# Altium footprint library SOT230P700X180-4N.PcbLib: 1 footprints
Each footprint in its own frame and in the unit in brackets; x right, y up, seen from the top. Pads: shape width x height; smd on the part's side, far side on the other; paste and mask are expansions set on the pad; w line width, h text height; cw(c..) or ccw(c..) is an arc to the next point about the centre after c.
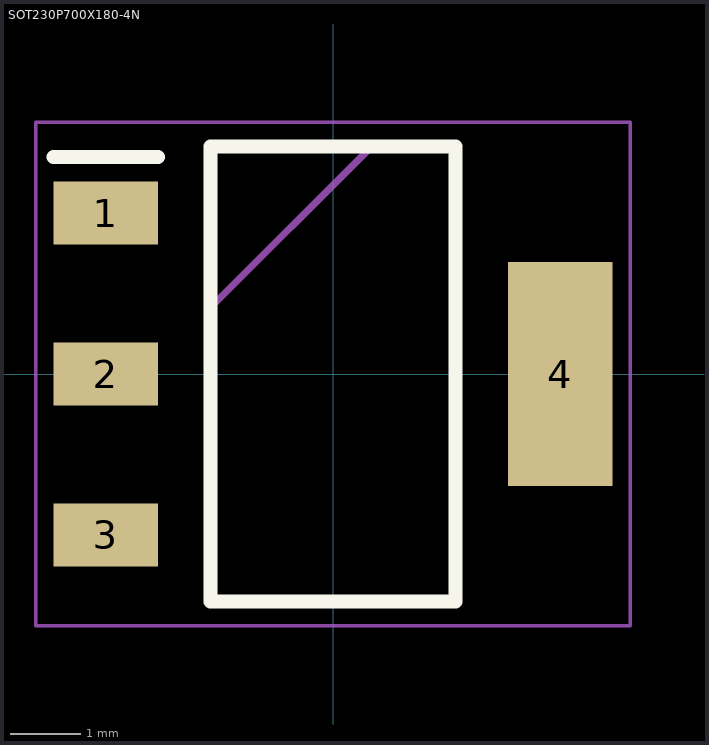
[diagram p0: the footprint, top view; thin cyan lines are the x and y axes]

## SOT230P700X180-4N [mm]
pads (4):
  rect 1.5x0.9 smd: 1(-3.25,2.3) 2(-3.25,0) 3(-3.25,-2.3)
  rect 1.5x3.2 smd: 4(3.25,0)
Top Overlay:
  lines w0.2: -4,3.1 -2.5,3.1 ; -1.75,-3.25 1.75,-3.25 1.75,3.25 -1.75,3.25 -1.75,-3.25
Mechanical 15:
  lines w0.1: -1.75,0.95 0.55,3.25 ; -1.75,-3.25 1.75,-3.25 1.75,3.25 -1.75,3.25 -1.75,-3.25
Mechanical 20:
  lines w0.05: -4.25,-3.6 4.25,-3.6 4.25,3.6 -4.25,3.6 -4.25,-3.6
